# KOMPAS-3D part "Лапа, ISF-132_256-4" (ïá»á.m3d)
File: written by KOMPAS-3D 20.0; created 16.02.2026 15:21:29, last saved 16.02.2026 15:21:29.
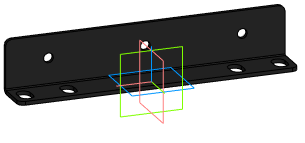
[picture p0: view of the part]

Document properties: Автор: admin; Полное имя файла: P:\INSTART\Технический отдел\ОР\Прочие задачи\КД на номенклатурный ряд\КД на типоразмеры дросселей\Сетевые дроссели ISF\ISF-4\Тип 1\ISF-132_256-4\0723\Новая папка\Лапа.m3d

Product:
- Part/product: Лапа  | designation ISF-132_256-4

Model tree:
1. Операция без истории:1

Expressions: ISF-132_256-4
